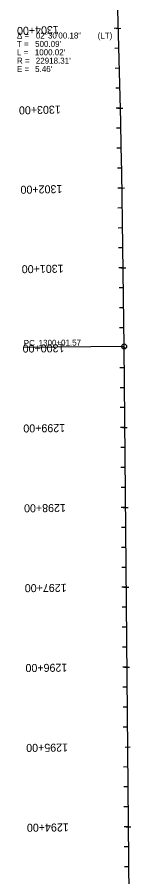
# Model space of a CAD drawing. Extents: x 19548215 to 19548727, y 7547983 to 7562114.
# Drawn here: x 19548311 to 19548455, y 7551338 to 7552414 of the extents above; entities that cross this region are included whole.
import ezdxf

# ---------------------------------------------------------------- set-up
doc = ezdxf.new("R2010")
doc.units = 0
for name, color, linetype in [('Contours Major', 7, 'Continuous'), ('Contours Minor', 7, 'Continuous'), ('Default', 7, 'Continuous'), ('TextAlignment', 7, 'Continuous'), ('TextAlignmentSml', 7, 'Continuous')]:
    doc.layers.add(name, color=color, linetype=linetype)

msp = doc.modelspace()

# ---------------------------------------------------------------- linework, layer by layer
at = {"layer": 'Contours Major'}
for p, q in [((19548438, 7552400.5), (19548432.5, 7552400.3)), ((19548440.4, 7552300.5), (19548434.9, 7552300.4)), ((19548442.4, 7552200.5), (19548436.9, 7552200.4)), ((19548443.9, 7552100.5), (19548438.5, 7552100.5)), ((19548442, 7552000.5), (19548448.1, 7552000.6)), ((19548445.9, 7551900.5), (19548440.5, 7551900.5)), ((19548446.8, 7551800.5), (19548441.4, 7551800.5)), ((19548447.7, 7551700.5), (19548442.3, 7551700.5)), ((19548448.6, 7551600.5), (19548443.2, 7551600.5)), ((19548446.5, 7551500.5), (19548452.6, 7551500.6)), ((19548450.4, 7551400.6), (19548445, 7551400.5))]:
    msp.add_line(p, q, dxfattribs=at)
at = {"layer": 'Contours Minor'}
msp.add_line((19548454.7, 7550927.2), (19548445, 7552002.1), dxfattribs=at)
msp.add_arc((19525527.6, 7551795.6), 22918.3, 0.51637, 3.01642, dxfattribs=at)
at = {"layer": 'Default'}
msp.add_line((19548454.7, 7550927.2), (19548445, 7552002.1), dxfattribs=at)
msp.add_arc((19525527.6, 7551795.6), 22918.3, 0.51637, 3.01642, dxfattribs=at)
at = {"layer": 'TextAlignment'}
for p in [(19548445, 7552002.1), (19548319, 7552001)]:
    msp.add_line(p, (19548319, 7552001), dxfattribs=at)
msp.add_circle((19548445, 7552002.1), 3.12, dxfattribs=at)
at = {"layer": 'TextAlignmentSml'}
for p, q in [((19548434.9, 7552400.4), (19548441, 7552400.5)), ((19548438.6, 7552375.5), (19548433.2, 7552375.3)), ((19548439.2, 7552350.5), (19548433.8, 7552350.3)), ((19548439.8, 7552325.5), (19548434.4, 7552325.4)), ((19548437.3, 7552300.4), (19548443.4, 7552300.6)), ((19548440.9, 7552275.5), (19548435.5, 7552275.4)), ((19548441.4, 7552250.5), (19548436, 7552250.4)), ((19548441.9, 7552225.5), (19548436.5, 7552225.4)), ((19548439.3, 7552200.5), (19548445.4, 7552200.6)), ((19548442.8, 7552175.5), (19548437.3, 7552175.4)), ((19548443.2, 7552150.5), (19548437.7, 7552150.4)), ((19548443.6, 7552125.5), (19548438.1, 7552125.4)), ((19548440.9, 7552100.5), (19548447, 7552100.6)), ((19548444.2, 7552075.5), (19548438.8, 7552075.5)), ((19548444.5, 7552050.5), (19548439.1, 7552050.5)), ((19548444.8, 7552025.5), (19548439.3, 7552025.5)), ((19548442, 7552000.5), (19548448.1, 7552000.6)), ((19548445.3, 7551975.5), (19548439.8, 7551975.5)), ((19548445.5, 7551950.5), (19548440, 7551950.5)), ((19548445.7, 7551925.5), (19548440.2, 7551925.5)), ((19548442.9, 7551900.5), (19548449, 7551900.6)), ((19548446.2, 7551875.5), (19548440.7, 7551875.5)), ((19548446.4, 7551850.5), (19548440.9, 7551850.5)), ((19548446.6, 7551825.5), (19548441.1, 7551825.5)), ((19548443.8, 7551800.5), (19548449.9, 7551800.6)), ((19548447.1, 7551775.5), (19548441.6, 7551775.5)), ((19548447.3, 7551750.5), (19548441.8, 7551750.5)), ((19548447.5, 7551725.5), (19548442.1, 7551725.5)), ((19548444.7, 7551700.5), (19548450.8, 7551700.6)), ((19548448, 7551675.5), (19548442.5, 7551675.5)), ((19548448.2, 7551650.5), (19548442.7, 7551650.5)), ((19548448.4, 7551625.5), (19548443, 7551625.5)), ((19548445.6, 7551600.5), (19548451.7, 7551600.6)), ((19548448.9, 7551575.5), (19548443.4, 7551575.5)), ((19548449.1, 7551550.5), (19548443.6, 7551550.5)), ((19548449.3, 7551525.5), (19548443.9, 7551525.5)), ((19548446.5, 7551500.5), (19548452.6, 7551500.6)), ((19548449.8, 7551475.6), (19548444.3, 7551475.5)), ((19548450, 7551450.6), (19548444.5, 7551450.5)), ((19548450.2, 7551425.6), (19548444.8, 7551425.5)), ((19548447.4, 7551400.5), (19548453.5, 7551400.6)), ((19548450.7, 7551375.6), (19548445.2, 7551375.5)), ((19548450.9, 7551350.6), (19548445.4, 7551350.5))]:
    msp.add_line(p, q, dxfattribs=at)

# ---------------------------------------------------------------- texts
at = {"layer": 'Contours Major'}
for s, p in [('1300+00', (19548370, 7552004.9)), ('1295+00', (19548374.5, 7551504.9))]:
    msp.add_text(s, height=10.02, rotation=180.5164, dxfattribs=at).set_placement(p)
at = {"layer": 'TextAlignment'}
for s, p in [('Δ = ', (19548310.4, 7552387.7)), ('02°30\'00.18"', (19548334.2, 7552387.7)), (' (LT)', (19548409, 7552387.7)), ('T = ', (19548310.4, 7552377.2)), ("500.09'", (19548333.2, 7552377.2)), ('L = ', (19548310.4, 7552366.7)), ("1000.02'", (19548332.8, 7552366.7)), ('R = ', (19548310.4, 7552356.2)), ("22918.31'", (19548334.1, 7552356.2)), ('E = ', (19548310.4, 7552345.7)), ("5.46'", (19548333.2, 7552345.7))]:
    msp.add_text(s, height=7.5, dxfattribs=at).set_placement(p)
for s, p in [('PC', (19548319, 7552002.6)), ('1300+01.57', (19548337.7, 7552002.8))]:
    msp.add_text(s, height=7.5, rotation=0.5164, dxfattribs=at).set_placement(p)
at = {"layer": 'TextAlignmentSml'}
for s, rotation, p in [('1304+00', 181.5124, (19548362.9, 7552403.5)), ('1303+00', 181.2624, (19548365.3, 7552303.8)), ('1302+00', 181.0124, (19548367.3, 7552204.2)), ('1301+00', 180.7624, (19548368.9, 7552104.5)), ('1300+00', 180.5164, (19548370, 7552004.9)), ('1299+00', 180.5164, (19548370.9, 7551904.9)), ('1298+00', 180.5164, (19548371.8, 7551804.9)), ('1297+00', 180.5164, (19548372.7, 7551704.9)), ('1296+00', 180.5164, (19548373.6, 7551604.9)), ('1295+00', 180.5164, (19548374.5, 7551504.9)), ('1294+00', 180.5164, (19548375.4, 7551404.9))]:
    msp.add_text(s, height=10.02, rotation=rotation, dxfattribs=at).set_placement(p)

doc.saveas('drawing.dxf')
